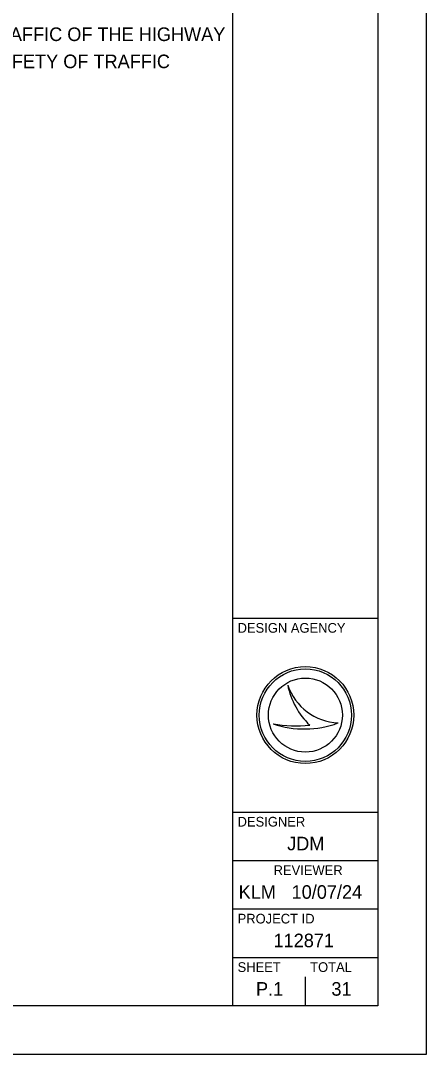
# Model space of a CAD drawing. Extents: x 0 to 36.5, y 0 to 25.3.
# Drawn here: x 29.81 to 34, y 0 to 10.67 of the extents above; entities that cross this region are included whole.
import ezdxf

# ---------------------------------------------------------------- set-up
doc = ezdxf.new("R2010")
doc.units = 0
for name, color, linetype in [('SH_Border', 7, 'Continuous'), ('SH_Cut_Line', 7, 'Continuous'), ('SH_Data', 7, 'Continuous')]:
    doc.layers.add(name, color=color, linetype=linetype)

msp = doc.modelspace()

# ---------------------------------------------------------------- linework, layer by layer
at = {"layer": 'SH_Border'}
for p, q in [((32, 0.5), (32, 21.5)), ((32, 4.5), (33.5, 4.5)), ((32, 2.5), (33.5, 2.5)), ((32, 2), (33.5, 2)), ((32, 1.5), (33.5, 1.5)), ((32, 1), (33.5, 1))]:
    msp.add_line(p, q, dxfattribs=at)
msp.add_lwpolyline([(1.5, 21.5), (33.5, 21.5), (33.5, 0.5), (1.5, 0.5)], close=True, dxfattribs=at)
at = {"layer": 'SH_Cut_Line'}
msp.add_lwpolyline([(0, 0), (34, 0), (34, 22), (0, 22)], close=True, dxfattribs=at)
at = {"layer": 'SH_Data'}
for p, q in [((32.567, 3.81), (32.567, 3.81)), ((32.75, 3.5), (32.75, 3.5)), ((33.087, 3.419), (33.087, 3.419)), ((32.417, 3.41), (32.417, 3.41)), ((32.75, 0.5), (32.75, 0.8)), ((32.375, 0.675), (32.375, 0.675))]:
    msp.add_line(p, q, dxfattribs=at)
for radius in [0.5, 0.477, 0.477, 0.382]:
    msp.add_circle((32.75, 3.5), radius, dxfattribs=at)
for centre, radius, start, end in [((33.116, 3.998), 0.58, 198.9257, 198.9319), ((33.347, 3.97), 0.796, 191.6379, 191.6421), ((33.116, 3.998), 0.58, 198.9319, 267.1657), ((33.347, 3.97), 0.796, 191.6421, 226.0947), ((32.739, 4.37), 1.013, 251.4576, 290.0832), ((32.648, 4.654), 1.266, 259.4964, 259.4995), ((32.739, 4.37), 1.013, 251.4527, 251.4576), ((32.648, 4.654), 1.266, 259.4995, 276.6672)]:
    msp.add_arc(centre, radius, start, end, dxfattribs=at)

# ---------------------------------------------------------------- texts
for s, height, p in [('IMPROVEMENT WILL NOT REQUIRE THE CLOSING TO TRAFFIC OF THE HIGHWAY', 0.14, (24.528, 10.455)), ('AND THAT PROVISIONS FOR THE MAINTENANCE AND SAFETY OF TRAFFIC', 0.14, (24.528, 10.175)), ('DESIGN AGENCY', 0.1, (32.05, 4.35)), ('DESIGNER', 0.1, (32.05, 2.35)), ('JDM', 0.14, (32.562, 2.105)), ('REVIEWER', 0.1, (32.422, 1.85)), ('KLM', 0.14, (32.061, 1.605)), ('10/07/24', 0.14, (32.608, 1.605)), ('PROJECT ID', 0.1, (32.05, 1.35)), ('112871', 0.14, (32.421, 1.105)), ('SHEET', 0.1, (32.05, 0.85)), ('TOTAL', 0.1, (32.8, 0.85)), ('31', 0.14, (33.019, 0.605)), ('P.1', 0.14, (32.24, 0.605))]:
    msp.add_text(s, height=height, dxfattribs=at).set_placement(p)

doc.saveas('drawing.dxf')
